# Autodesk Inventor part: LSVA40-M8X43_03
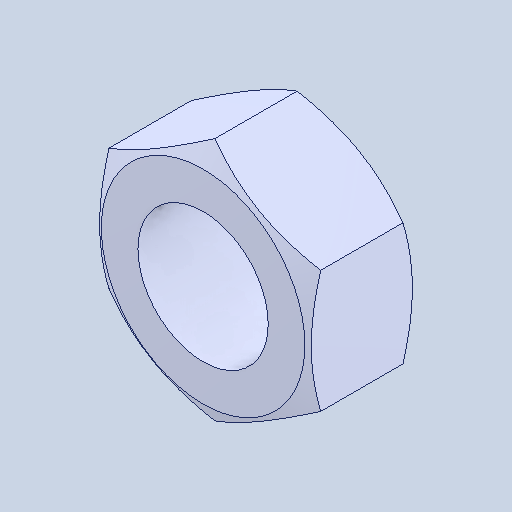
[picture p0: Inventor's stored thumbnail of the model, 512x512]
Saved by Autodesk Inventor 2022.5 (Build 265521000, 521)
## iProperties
Created: 2024-08
Part Number: LSVA40-M8X43_03
Material: 一般
Document SubType Name: Modeling
Designer: ImaoCorp
Density: 1 g/cm^3
Appearance: 既定
Author: ImaoCorp
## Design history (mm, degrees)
feature "LSVA40-M8X43_03"
node "ソリッド1"
